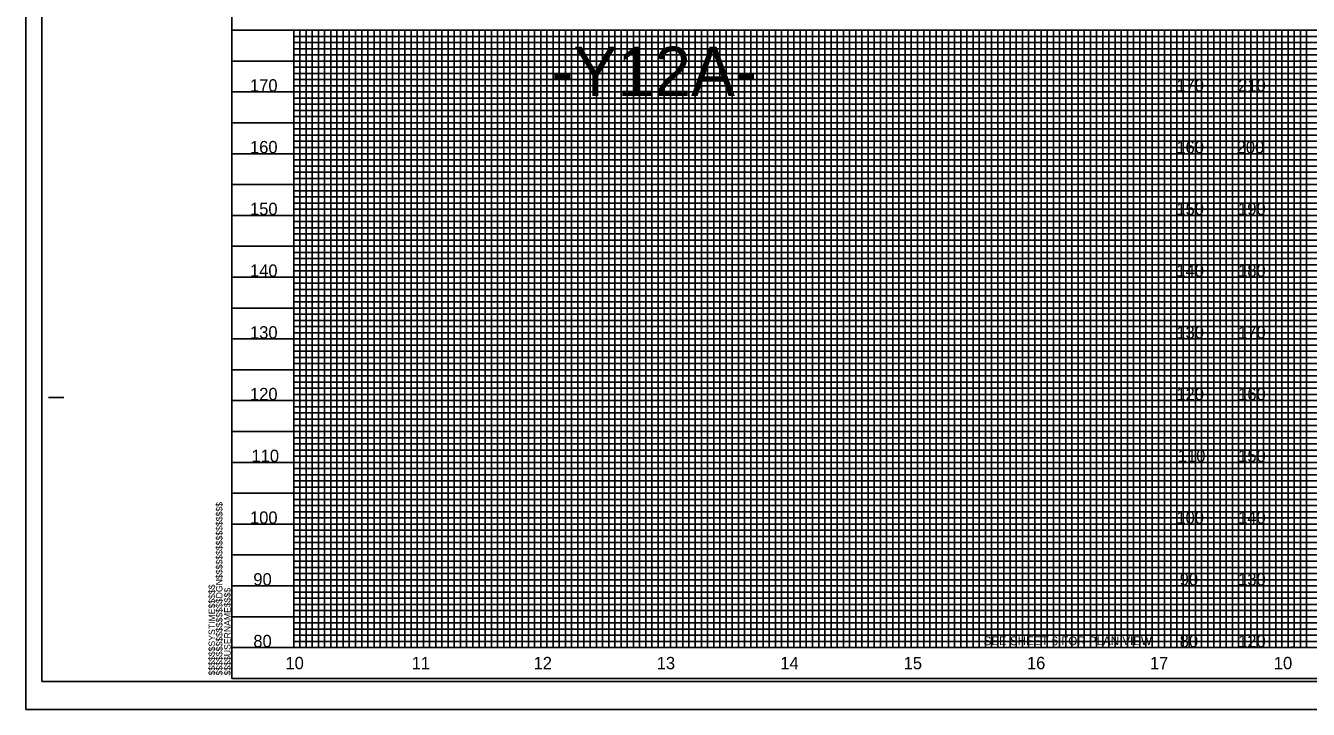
# Model space of a CAD drawing. Extents: x 1779926 to 1781610, y 605564 to 621564.
# Drawn here: x 1779926 to 1780964, y 605564 to 606118 of the extents above; entities that cross this region are included whole.
import ezdxf

# ---------------------------------------------------------------- set-up
doc = ezdxf.new("R2010")
doc.units = 0
for name, color, linetype in [('Exist Vertical Profile Horizontal Axis Label Major', 7, 'Continuous'), ('Exist Vertical Profile Vertical Axis Label', 7, 'Continuous'), ('Prop DSN Text', 7, 'Continuous'), ('Prop Grid Mask', 7, 'Continuous'), ('Scratch_Level_0', 7, 'Continuous'), ('Sheet DOT Grid CELL', 7, 'Continuous'), ('Sheet Layout Profile Border Port 2', 7, 'Continuous'), ('Sheet Plot Border Inside CELL', 7, 'Continuous'), ('Sheet Plot Border Outside CELL', 7, 'Continuous'), ('Sheet Profile CELL', 7, 'Continuous'), ('Sheet Profile Grid Major CELL', 7, 'Continuous'), ('Sheet Profile Grid Middle CELL', 7, 'Continuous'), ('Sheet Profile Grid Minor CELL', 7, 'Continuous')]:
    doc.layers.add(name, color=color, linetype=linetype)

msp = doc.modelspace()

# ---------------------------------------------------------------- linework, layer by layer
at = {"layer": 'Prop Grid Mask'}
for points in [[(1780843, 606114.2), (1780893, 606114.2), (1780893, 605614.2), (1780843, 605614.2)], [(1780893, 606114.2), (1780943, 606114.2), (1780943, 605614.2), (1780893, 605614.2)], [(1780343, 606104.2), (1780533, 606104.2), (1780533, 606054.2), (1780343, 606054.2)], [(1780843, 605624.2), (1780698, 605624.2), (1780698, 605614.2), (1780843, 605614.2)]]:
    msp.add_lwpolyline(points, close=True, dxfattribs=at)
at = {"layer": 'Scratch_Level_0'}
msp.add_lwpolyline([(1780143, 605614.2), (1780143, 606114.2), (1781543, 606114.2), (1781543, 605614.2)], close=True, dxfattribs=at)
at = {"layer": 'Sheet DOT Grid CELL'}
for p, q in [((1780093, 606114.2), (1781592.8, 606114.2)), ((1780143, 606114.2), (1780143, 605614.2)), ((1780193, 606114.2), (1780193, 605614.2)), ((1780243, 606114.2), (1780243, 605614.2)), ((1780293, 606114.2), (1780293, 605614.2)), ((1780343, 606114.2), (1780343, 605614.2)), ((1780393, 606114.2), (1780393, 605614.2)), ((1780443, 606114.2), (1780443, 605614.2)), ((1780493, 606114.2), (1780493, 605614.2)), ((1780543, 606114.2), (1780543, 605614.2)), ((1780593, 606114.2), (1780593, 605614.2)), ((1780643, 606114.2), (1780643, 605614.2)), ((1780693, 606114.2), (1780693, 605614.2)), ((1780743, 606114.2), (1780743, 605614.2)), ((1780793, 606114.2), (1780793, 605614.2)), ((1780843, 606114.2), (1780843, 605614.2)), ((1780893, 606114.2), (1780893, 605614.2)), ((1780893, 606114.2), (1780893, 605614.2)), ((1780943, 606114.2), (1780943, 605614.2)), ((1780943, 606114.2), (1780943, 605614.2)), ((1780093, 606064.2), (1781592.8, 606064.2)), ((1780093, 606014.2), (1781592.8, 606014.2)), ((1780093, 605964.2), (1781592.8, 605964.2)), ((1780093, 605914.2), (1781592.8, 605914.2)), ((1780093, 605864.2), (1781592.8, 605864.2)), ((1780093, 605814.2), (1781592.8, 605814.2)), ((1780093, 605764.2), (1781592.8, 605764.2)), ((1780093, 605714.2), (1781592.8, 605714.2)), ((1780093, 605664.2), (1781592.8, 605664.2))]:
    msp.add_line(p, q, dxfattribs=at)
at = {"layer": 'Sheet Layout Profile Border Port 2'}
for points in [[(1780143, 606114.2), (1781543, 606114.2), (1781543, 605614.2), (1780143, 605614.2)], [(1780143, 606114.2), (1780843, 606114.2), (1780843, 605614.2), (1780143, 605614.2)]]:
    msp.add_lwpolyline(points, close=True, dxfattribs=at)
at = {"layer": 'Sheet Plot Border Inside CELL'}
msp.add_lwpolyline([(1779939, 605586.7), (1781605.5, 605586.7), (1781605.5, 606641.8), (1779939, 606641.8)], close=True, dxfattribs=at)
at = {"layer": 'Sheet Plot Border Outside CELL'}
msp.add_lwpolyline([(1779926, 605564.2), (1781610, 605564.2), (1781610, 606664.2), (1779926, 606664.2)], close=True, dxfattribs=at)
at = {"layer": 'Sheet Profile CELL'}
for p, q in [((1780093, 606114.2), (1781593, 606114.2)), ((1779944.5, 605816.7), (1779957, 605816.7)), ((1781593, 605614.2), (1780093, 605614.2)), ((1780093, 605589.2), (1781593, 605589.2)), ((1780093, 605589.2), (1780093, 605589.2)), ((1780093, 605589.2), (1780093, 605589.2)), ((1780093, 605589.2), (1780093, 605589.2)), ((1780093, 605589.2), (1780093, 605589.2)), ((1780093, 605589.2), (1780093, 605589.2)), ((1780093, 605589.2), (1780093, 605589.2)), ((1780093, 605589.2), (1780093, 605589.2))]:
    msp.add_line(p, q, dxfattribs=at)
msp.add_lwpolyline([(1781593, 606639.2), (1780093, 606639.2), (1780093, 605589.2), (1781593, 605589.2)], close=True, dxfattribs=at)
msp.add_lwpolyline([(1780130.5, 605589.2), (1780130.5, 605589.2)], dxfattribs=at)
at = {"layer": 'Sheet Profile Grid Major CELL'}
for p, q in [((1780593, 606114.2), (1780643, 606114.2)), ((1780693, 606114.2), (1780743, 606114.2)), ((1780793, 606114.2), (1780843, 606114.2)), ((1780893, 606114.2), (1780943, 606114.2)), ((1780093, 605614.2), (1780093, 605614.2))]:
    msp.add_line(p, q, dxfattribs=at)
for points in [[(1780143, 606114.2), (1780143, 605614.2), (1780193, 605614.2), (1780193, 606114.2), (1780243, 606114.2), (1780243, 605614.2), (1780293, 605614.2), (1780293, 606114.2), (1780343, 606114.2), (1780343, 605614.2), (1780393, 605614.2), (1780393, 606114.2), (1780443, 606114.2), (1780443, 605614.2), (1780493, 605614.2), (1780493, 606114.2), (1780543, 606114.2), (1780543, 605614.2), (1780593, 605614.2), (1780593, 606114.2), (1780643, 606114.2), (1780643, 605614.2), (1780693, 605614.2), (1780693, 606114.2), (1780743, 606114.2), (1780743, 605614.2), (1780793, 605614.2), (1780793, 606114.2), (1780843, 606114.2), (1780843, 605614.2), (1780893, 605614.2), (1780893, 606114.2), (1780943, 606114.2), (1780943, 605614.2), (1780993, 605614.2)], [(1781593, 606064.2), (1780093, 606064.2)], [(1781593, 606014.2), (1780093, 606014.2), (1780093, 605964.2), (1781593, 605964.2)], [(1781593, 605914.2), (1780093, 605914.2), (1780093, 605864.2), (1781593, 605864.2)], [(1781593, 605814.2), (1780093, 605814.2), (1780093, 605764.2), (1781593, 605764.2)], [(1781593, 605714.2), (1780093, 605714.2), (1780093, 605714.2), (1780093, 605664.2), (1781593, 605664.2)], [(1781593, 605614.2), (1780093, 605614.2)]]:
    msp.add_lwpolyline(points, dxfattribs=at)
at = {"layer": 'Sheet Profile Grid Middle CELL'}
for points in [[(1780118, 606114.2), (1780168, 606114.2), (1780168, 605614.2), (1780218, 605614.2), (1780218, 606114.2), (1780268, 606114.2), (1780268, 605614.2), (1780318, 605614.2), (1780318, 606114.2), (1780368, 606114.2), (1780368, 605614.2), (1780418, 605614.2), (1780418, 606114.2), (1780468, 606114.2), (1780468, 605614.2), (1780518, 605614.2), (1780518, 606114.2), (1780568, 606114.2), (1780568, 605614.2), (1780618, 605614.2), (1780618, 606114.2), (1780668, 606114.2), (1780668, 605614.2), (1780718, 605614.2), (1780718, 605614.2), (1780718, 606114.2), (1780768, 606114.2), (1780768, 605614.2), (1780818, 605614.2), (1780818, 606114.2), (1780868, 606114.2), (1780868, 605614.2), (1780918, 605614.2), (1780918, 606114.2), (1780968, 606114.2)], [(1780093, 606089.2), (1781593, 606089.2)], [(1781593, 606039.2), (1780093, 606039.2), (1780093, 605989.2), (1781593, 605989.2)], [(1781593, 605939.2), (1780093, 605939.2), (1780093, 605889.2), (1781593, 605889.2)], [(1781593, 605839.2), (1780093, 605839.2), (1780093, 605789.2), (1781593, 605789.2)], [(1781593, 605739.2), (1780093, 605739.2), (1780093, 605689.2), (1781593, 605689.2)], [(1781593, 605639.2), (1780093, 605639.2)]]:
    msp.add_lwpolyline(points, dxfattribs=at)
at = {"layer": 'Sheet Profile Grid Minor CELL'}
for p, q in [((1780143, 606109.2), (1781543, 606109.2)), ((1781543, 606104.2), (1780143, 606104.2)), ((1780143, 606099.2), (1781543, 606099.2)), ((1781543, 606094.2), (1780143, 606094.2)), ((1780143, 606084.2), (1781543, 606084.2)), ((1781543, 606079.2), (1780143, 606079.2)), ((1780143, 606074.2), (1781543, 606074.2)), ((1781543, 606069.2), (1780143, 606069.2)), ((1780143, 606059.2), (1781543, 606059.2)), ((1781543, 606054.2), (1780143, 606054.2)), ((1780143, 606049.2), (1781543, 606049.2)), ((1781543, 606044.2), (1780143, 606044.2)), ((1780143, 606034.2), (1781543, 606034.2)), ((1781543, 606029.2), (1780143, 606029.2)), ((1780143, 606024.2), (1781543, 606024.2)), ((1781543, 606019.2), (1780143, 606019.2)), ((1780143, 606009.2), (1781543, 606009.2)), ((1781543, 606004.2), (1780143, 606004.2)), ((1780143, 605999.2), (1781543, 605999.2)), ((1781543, 605994.2), (1780143, 605994.2)), ((1780143, 605984.2), (1781543, 605984.2)), ((1781543, 605979.2), (1780143, 605979.2)), ((1780143, 605974.2), (1781543, 605974.2)), ((1781543, 605969.2), (1780143, 605969.2)), ((1780143, 605959.2), (1781543, 605959.2)), ((1781543, 605954.2), (1780143, 605954.2)), ((1780143, 605949.2), (1781543, 605949.2)), ((1781543, 605944.2), (1780143, 605944.2)), ((1780143, 605934.2), (1781543, 605934.2)), ((1781543, 605929.2), (1780143, 605929.2)), ((1780143, 605924.2), (1781543, 605924.2)), ((1781543, 605919.2), (1780143, 605919.4)), ((1780143, 605909.2), (1781543, 605909.2)), ((1781543, 605904.2), (1780143, 605904.2)), ((1780143, 605899.2), (1781543, 605899.2)), ((1781543, 605894.2), (1780143, 605894.2)), ((1780143, 605884.2), (1781543, 605884.2)), ((1781543, 605879.2), (1780143, 605879.2)), ((1780143, 605874.2), (1781543, 605874.2)), ((1781543, 605869.2), (1780143, 605869.2)), ((1780143, 605859.2), (1781543, 605859.2)), ((1781543, 605854.2), (1780143, 605854.2)), ((1780143, 605849.2), (1781543, 605849.2)), ((1781543, 605844.2), (1780143, 605844.2)), ((1780143, 605834.2), (1781543, 605834.2)), ((1781543, 605829.2), (1780143, 605829.2)), ((1780143, 605824.2), (1781543, 605824.2)), ((1781543, 605819.2), (1780143, 605819.2)), ((1780143, 605809.2), (1781543, 605809.2)), ((1781543, 605804.2), (1780143, 605804.2)), ((1780143, 605799.2), (1781543, 605799.2)), ((1781543, 605794.2), (1780143, 605794.2)), ((1780143, 605784.2), (1781543, 605784.2)), ((1781543, 605779.2), (1780143, 605779.2)), ((1780143, 605774.2), (1781543, 605774.2)), ((1781543, 605769.2), (1780143, 605769.2)), ((1780143, 605759.2), (1781543, 605759.2)), ((1781543, 605754.2), (1780143, 605754.2)), ((1780143, 605749.2), (1781543, 605749.2)), ((1781543, 605744.2), (1780143, 605744.2)), ((1780143, 605734.2), (1781543, 605734.2)), ((1781543, 605729.2), (1780143, 605729.2)), ((1780143, 605724.2), (1781543, 605724.2)), ((1781543, 605719.2), (1780143, 605719.2)), ((1780143, 605709.2), (1781543, 605709.2)), ((1781543, 605704.2), (1780143, 605704.2)), ((1780143, 605699.2), (1781543, 605699.2)), ((1781543, 605694.2), (1780143, 605694.2)), ((1780143, 605684.2), (1781543, 605684.2)), ((1781543, 605679.2), (1780143, 605679.2)), ((1780143, 605674.2), (1781543, 605674.2)), ((1781543, 605669.2), (1780143, 605669.2)), ((1780143, 605659.2), (1781543, 605659.2)), ((1781543, 605654.2), (1780143, 605654.2)), ((1780143, 605649.2), (1781543, 605649.2)), ((1781543, 605644.2), (1780143, 605644.2)), ((1780143, 605634.2), (1781543, 605634.2)), ((1781543, 605629.2), (1780143, 605629.2)), ((1780143, 605624.2), (1781543, 605624.2)), ((1780143, 605619.2), (1781543, 605619.2))]:
    msp.add_line(p, q, dxfattribs=at)
for points in [[(1780143, 606114.2), (1780148, 606114.2), (1780148, 605614.2), (1780153, 605614.2), (1780153, 606114.2), (1780158, 606114.2), (1780158, 605614.2), (1780163, 605614.2), (1780163, 606114.2), (1780173, 606114.2), (1780173, 605614.2), (1780178, 605614.2), (1780178, 606114.2), (1780183, 606114.2), (1780183, 605614.2), (1780188, 605614.2), (1780198, 605614.2), (1780203, 605614.2), (1780203, 606114.2), (1780208, 606114.2), (1780208, 605614.2), (1780213, 605614.2), (1780213, 606114.2), (1780223, 606114.2), (1780223, 605614.2), (1780228, 605614.2), (1780228, 606114.2), (1780233, 606114.2), (1780233, 605614.2), (1780238, 605614.2), (1780238, 606114.2), (1780248, 606114.2), (1780248, 605614.2), (1780253, 605614.2), (1780253, 606114.2), (1780258, 606114.2), (1780258, 605614.2), (1780263, 605614.2), (1780263, 606114.2), (1780273, 606114.2), (1780273, 605614.2), (1780278, 605614.2), (1780278, 606114.2), (1780283, 606114.2), (1780283, 605614.2), (1780288, 605614.2), (1780288, 606114.2), (1780298, 606114.2), (1780298, 605614.2), (1780303, 605614.2), (1780303, 606114.2), (1780308, 606114.2), (1780308, 605614.2), (1780313, 605614.2), (1780313, 606114.2), (1780323, 606114.2), (1780323, 605614.2), (1780328, 605614.2), (1780328, 606114.2), (1780333, 606114.2), (1780333, 605614.2), (1780338, 605614.2), (1780338, 606114.2), (1780348, 606114.2), (1780348, 605614.2), (1780353, 605614.2), (1780353, 606114.2), (1780358, 606114.2), (1780358, 605614.2)], [(1780188, 605614.2), (1780188, 606114.2), (1780198, 606114.2), (1780198, 605614.2)], [(1780358, 605614.2), (1780363, 605614.2), (1780363, 606114.2), (1780373, 606114.2), (1780373, 605614.2), (1780378, 605614.2), (1780378, 606114.2), (1780383, 606114.2), (1780383, 605614.2), (1780388, 605614.2), (1780388, 606114.2), (1780398, 606114.2), (1780398, 605614.2), (1780403, 605614.2), (1780403, 606114.2), (1780408, 606114.2), (1780408, 605614.2), (1780413, 605614.2), (1780413, 606114.2), (1780423, 606114.2), (1780423, 605614.2), (1780428, 605614.2), (1780428, 606114.2), (1780433, 606114.2), (1780433, 605614.2), (1780438, 605614.2), (1780438, 606114.2), (1780448, 606114.2), (1780448, 605614.2), (1780453, 605614.2), (1780453, 606114.2), (1780458, 606114.2), (1780458, 605614.2), (1780463, 605614.2), (1780463, 606114.2), (1780473, 606114.2), (1780473, 605614.2), (1780478, 605614.2), (1780478, 606114.2), (1780483, 606114.2), (1780483, 605614.2), (1780488, 605614.2), (1780488, 606114.2), (1780498, 606114.2), (1780498, 605614.2), (1780503, 605614.2), (1780503, 606114.2), (1780508, 606114.2), (1780508, 605614.2), (1780513, 605614.2), (1780513, 606114.2), (1780523, 606114.2), (1780523, 605614.2), (1780528, 605614.2), (1780528, 606114.2), (1780533, 606114.2), (1780533, 605614.2), (1780538, 605614.2), (1780538, 606114.2), (1780548, 606114.2), (1780548, 605614.2), (1780553, 605614.2), (1780553, 606114.2), (1780558, 606114.2), (1780558, 605614.2), (1780563, 605614.2), (1780563, 606114.2), (1780573, 606114.2), (1780573, 605614.2), (1780578, 605614.2), (1780578, 606114.2), (1780583, 606114.2), (1780583, 605614.2), (1780588, 605614.2), (1780588, 606114.2), (1780598, 606114.2), (1780598, 605614.2), (1780603, 605614.2), (1780603, 606114.2), (1780608, 606114.2), (1780608, 605614.2), (1780613, 605614.2), (1780613, 606114.2), (1780623, 606114.2), (1780623, 605614.2), (1780628, 605614.2), (1780628, 606114.2), (1780633, 606114.2), (1780633, 605614.2), (1780638, 605614.2), (1780638, 606114.2), (1780648, 606114.2), (1780648, 605614.2), (1780653, 605614.2), (1780653, 606114.2), (1780658, 606114.2), (1780658, 605614.2), (1780663, 605614.2), (1780663, 606114.2), (1780673, 606114.2)], [(1780673, 606114.2), (1780673, 605614.2), (1780678, 605614.2), (1780678, 606114.2), (1780683, 606114.2), (1780683, 605614.2), (1780688, 605614.2), (1780688, 606114.2), (1780698, 606114.2), (1780698, 605614.2), (1780703, 605614.2), (1780703, 606114.2), (1780708, 606114.2), (1780708, 605614.2), (1780713, 605614.2), (1780713, 606114.2), (1780723, 606114.2), (1780723, 605614.2), (1780728, 605614.2), (1780728, 606114.2), (1780733, 606114.2), (1780733, 605614.2), (1780738, 605614.2), (1780738, 606114.2), (1780748, 606114.2), (1780748, 605614.2), (1780753, 605614.2), (1780753, 606114.2), (1780758, 606114.2), (1780758, 605614.2), (1780763, 605614.2), (1780763, 606114.2), (1780773, 606114.2), (1780773, 605614.2), (1780778, 605614.2), (1780778, 606114.2), (1780783, 606114.2), (1780783, 605614.2), (1780788, 605614.2), (1780788, 606114.2), (1780798, 606114.2), (1780798, 605614.2), (1780798, 605614.2), (1780803, 605614.2), (1780803, 606114.2), (1780808, 606114.2), (1780808, 605614.2), (1780813, 605614.2), (1780813, 606114.2), (1780823, 606114.2), (1780823, 605614.2), (1780828, 605614.2), (1780828, 606114.2), (1780833, 606114.2), (1780833, 605614.2), (1780838, 605614.2), (1780838, 606114.2), (1780848, 606114.2), (1780848, 605614.2), (1780853, 605614.2), (1780853, 606114.2), (1780858, 606114.2), (1780858, 605614.2), (1780863, 605614.2), (1780863, 606114.2), (1780873, 606114.2), (1780873, 605614.2), (1780878, 605614.2), (1780878, 606114.2), (1780883, 606114.2), (1780883, 605614.2), (1780888, 605614.2), (1780888, 606114.2), (1780898, 606114.2), (1780898, 605614.2), (1780903, 605614.2), (1780903, 606114.2), (1780908, 606114.2), (1780908, 605614.2), (1780913, 605614.2), (1780913, 606114.2), (1780923, 606114.2), (1780923, 605614.2), (1780928, 605614.2), (1780928, 606114.2), (1780933, 606114.2), (1780933, 605614.2), (1780938, 605614.2), (1780938, 606114.2), (1780948, 606114.2), (1780948, 605614.2), (1780952.7, 605614.8), (1780953, 605614.2), (1780953, 606114.2), (1780958, 606114.2), (1780958, 605614.2), (1780963, 605614.2), (1780963, 606114.2), (1780973, 606114.2)]]:
    msp.add_lwpolyline(points, dxfattribs=at)

# ---------------------------------------------------------------- texts
at = {"layer": 'Exist Vertical Profile Horizontal Axis Label Major'}
for s, p in [('10', (1780136.3, 605596.7)), ('11', (1780238.5, 605596.7)), ('12', (1780337.2, 605596.7)), ('13', (1780436.9, 605596.7)), ('14', (1780536.9, 605596.7)), ('15', (1780636.8, 605596.7)), ('16', (1780736.6, 605596.7)), ('17', (1780836.2, 605596.7)), ('10', (1780936.5, 605596.7))]:
    msp.add_text(s, height=10, dxfattribs=at).set_placement(p)
at = {"layer": 'Exist Vertical Profile Vertical Axis Label'}
for s, height, p in [('-Y12A-', 40, (1780351.6, 606060.8)), ('170', 10, (1780107.6, 606064.5)), ('170', 10, (1780857.6, 606064.5)), ('210', 10, (1780907.6, 606064.5)), ('160', 10, (1780107.6, 606014.5)), ('160', 10, (1780857.6, 606014.5)), ('200', 10, (1780906.4, 606014.5)), ('150', 10, (1780107.6, 605964.5)), ('150', 10, (1780857.6, 605964.5)), ('190', 10, (1780907.6, 605964.5)), ('140', 10, (1780107.6, 605914.5)), ('140', 10, (1780857.6, 605914.5)), ('180', 10, (1780907.6, 605914.5)), ('130', 10, (1780107.6, 605864.5)), ('130', 10, (1780857.6, 605864.5)), ('170', 10, (1780907.6, 605864.5)), ('120', 10, (1780107.6, 605814.5)), ('120', 10, (1780857.6, 605814.5)), ('160', 10, (1780907.6, 605814.5)), ('110', 10, (1780108.8, 605764.5)), ('110', 10, (1780858.8, 605764.5)), ('150', 10, (1780907.6, 605764.5)), ('100', 10, (1780107.6, 605714.5)), ('100', 10, (1780857.6, 605714.5)), ('140', 10, (1780907.6, 605714.5)), ('90', 10, (1780110.3, 605664.5)), ('90', 10, (1780860.3, 605664.5)), ('130', 10, (1780907.6, 605664.5)), ('80', 10, (1780110.3, 605614.5)), ('80', 10, (1780860.3, 605614.5)), ('120', 10, (1780907.6, 605614.5))]:
    msp.add_text(s, height=height, dxfattribs=at).set_placement(p)
at = {"layer": 'Prop DSN Text'}
msp.add_text('SEE SHEET 6 FOR PLAN VIEW', height=7, dxfattribs=at).set_placement((1780701.5, 605616.2))
at = {"layer": 'Sheet Profile CELL'}
for s, p in [('$$$$$$$$$$$$$$$$DGN$$$$$$$$$$$$$$$$', (1780085.3, 605591.6)), ('$$$$$$SYSTIME$$$$$', (1780079.3, 605591.6)), ('$$$$USERNAME$$$$', (1780091.9, 605591.6))]:
    msp.add_text(s, height=5.25, rotation=90, dxfattribs=at).set_placement(p)

doc.saveas('drawing.dxf')
